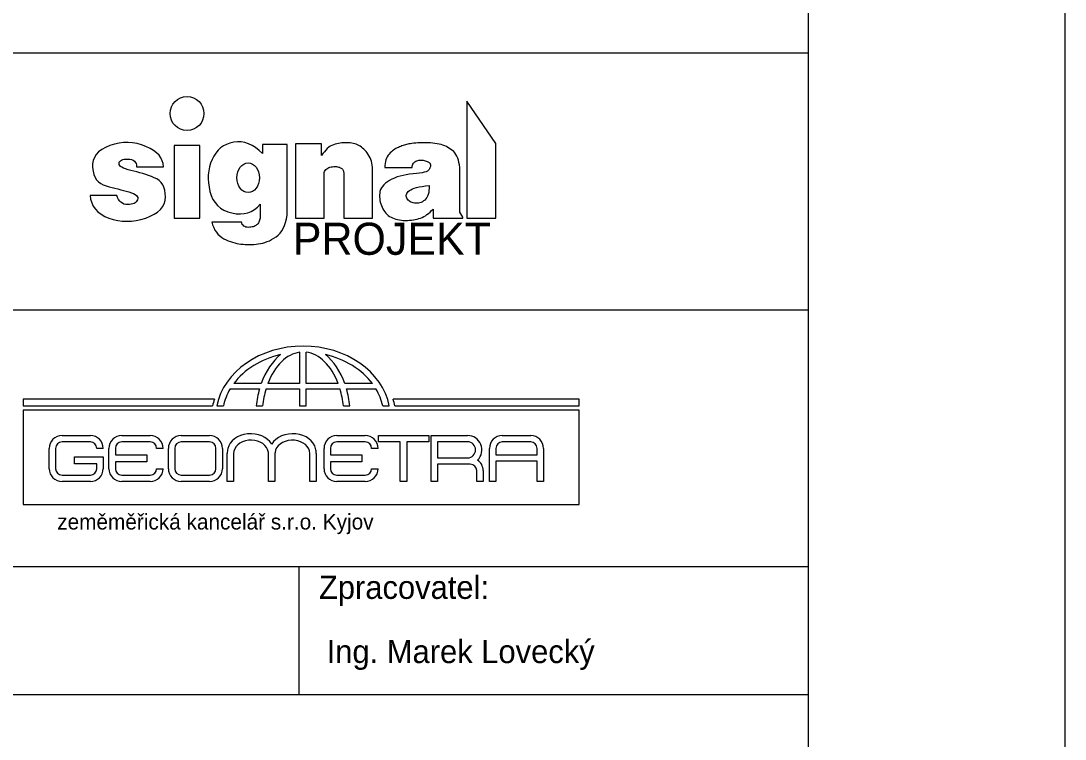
# Model space of a CAD drawing. Extents: x 3181 to 4881, y -3400 to -2956.
# Drawn here: x 4054.2 to 4135.6, y -3301.1 to -3245.1 of the extents above; entities that cross this region are included whole.
import ezdxf

# ---------------------------------------------------------------- set-up
doc = ezdxf.new("R2010")
doc.units = 0
for name, color, linetype in [('Default', 7, 'Continuous'), ('Vrstva 1', 7, 'Continuous'), ('Vrstva 11', 7, 'Continuous'), ('Vrstva 17', 7, 'Continuous'), ('Vrstva 6', 7, 'Continuous')]:
    doc.layers.add(name, color=color, linetype=linetype)

msp = doc.modelspace()

# ---------------------------------------------------------------- linework, layer by layer
at = {"layer": 'Default'}
msp.add_lwpolyline([(3925.563, -3399.617), (4135.563, -3399.617), (4135.563, -3102.617), (3925.563, -3102.617)], close=True, dxfattribs=at)
at = {"layer": 'Vrstva 1'}
msp.add_lwpolyline([(3945.563, -3122.617), (4115.563, -3122.617), (4115.563, -3382.617), (3945.563, -3382.617)], close=True, dxfattribs=at)
at = {"layer": 'Vrstva 11'}
for points in [[(4091.228, -3260.496), (4091.228, -3254.656), (4088.988, -3251.376), (4088.988, -3260.496), (4091.228, -3260.496)], [(4062.499, -3260.731), (4062.861, -3260.714), (4063.228, -3260.666), (4063.599, -3260.587), (4063.975, -3260.477), (4064.329, -3260.341), (4064.637, -3260.185), (4064.898, -3260.009), (4065.112, -3259.813), (4065.28, -3259.597), (4065.4, -3259.361), (4065.474, -3259.105), (4065.5, -3258.829), (4065.49, -3258.556), (4065.451, -3258.307), (4065.385, -3258.083), (4065.291, -3257.883), (4065.17, -3257.708), (4065.021, -3257.558), (4064.844, -3257.433), (4064.639, -3257.332), (4064.42, -3257.246), (4064.198, -3257.164), (4063.973, -3257.087), (4063.747, -3257.014), (4063.518, -3256.946), (4063.287, -3256.881), (4063.054, -3256.822), (4062.818, -3256.766), (4062.596, -3256.711), (4062.405, -3256.652), (4062.244, -3256.589), (4062.114, -3256.522), (4062.014, -3256.451), (4061.945, -3256.376), (4061.906, -3256.297), (4061.897, -3256.214), (4061.914, -3256.134), (4061.95, -3256.065), (4062.006, -3256.007), (4062.082, -3255.96), (4062.178, -3255.924), (4062.294, -3255.898), (4062.429, -3255.884), (4062.585, -3255.88), (4062.74, -3255.891), (4062.875, -3255.92), (4062.99, -3255.967), (4063.085, -3256.033), (4063.16, -3256.117), (4063.214, -3256.219), (4063.249, -3256.339), (4063.263, -3256.478), (4065.342, -3256.478), (4065.323, -3256.236), (4065.261, -3256.007), (4065.156, -3255.789), (4065.008, -3255.585), (4064.817, -3255.394), (4064.583, -3255.215), (4064.307, -3255.049), (4063.987, -3254.895), (4063.645, -3254.766), (4063.3, -3254.671), (4062.952, -3254.612), (4062.602, -3254.587), (4062.249, -3254.597), (4061.894, -3254.642), (4061.535, -3254.721), (4061.174, -3254.836), (4060.836, -3254.978), (4060.547, -3255.141), (4060.306, -3255.324), (4060.114, -3255.528), (4059.971, -3255.753), (4059.876, -3255.997), (4059.83, -3256.263), (4059.832, -3256.549), (4059.872, -3256.83), (4059.938, -3257.082), (4060.03, -3257.305), (4060.148, -3257.497), (4060.293, -3257.661), (4060.464, -3257.795), (4060.661, -3257.899), (4060.885, -3257.974), (4061.12, -3258.034), (4061.351, -3258.093), (4061.578, -3258.152), (4061.802, -3258.211), (4062.023, -3258.27), (4062.239, -3258.328), (4062.452, -3258.386), (4062.662, -3258.444), (4062.854, -3258.504), (4063.016, -3258.568), (4063.146, -3258.637), (4063.246, -3258.711), (4063.314, -3258.789), (4063.352, -3258.871), (4063.359, -3258.958), (4063.335, -3259.049), (4063.289, -3259.137), (4063.228, -3259.214), (4063.152, -3259.278), (4063.062, -3259.331), (4062.958, -3259.373), (4062.84, -3259.403), (4062.707, -3259.421), (4062.559, -3259.428), (4062.411, -3259.418), (4062.275, -3259.384), (4062.152, -3259.329), (4062.04, -3259.25), (4061.942, -3259.149), (4061.855, -3259.025), (4061.781, -3258.879), (4061.72, -3258.71), (4059.639, -3258.71), (4059.683, -3259.017), (4059.767, -3259.299), (4059.89, -3259.557), (4060.052, -3259.791), (4060.254, -3260), (4060.496, -3260.185), (4060.778, -3260.346), (4061.099, -3260.483), (4061.442, -3260.592), (4061.79, -3260.669), (4062.142, -3260.716), (4062.499, -3260.731)], [(4068.188, -3260.496), (4068.188, -3254.816), (4066.188, -3254.816), (4066.188, -3260.496), (4068.188, -3260.496)], [(4072.047, -3262.538), (4072.216, -3262.534), (4072.386, -3262.526), (4072.558, -3262.512), (4072.731, -3262.494), (4072.905, -3262.467), (4073.079, -3262.428), (4073.253, -3262.377), (4073.426, -3262.314), (4073.6, -3262.238), (4073.772, -3262.15), (4073.945, -3262.051), (4074.117, -3261.939), (4074.282, -3261.809), (4074.43, -3261.656), (4074.563, -3261.481), (4074.679, -3261.282), (4074.78, -3261.06), (4074.865, -3260.815), (4074.934, -3260.547), (4074.988, -3260.256), (4074.988, -3254.736), (4073.068, -3254.736), (4073.068, -3255.456), (4072.802, -3255.201), (4072.531, -3254.988), (4072.257, -3254.816), (4071.978, -3254.685), (4071.695, -3254.595), (4071.407, -3254.546), (4071.116, -3254.539), (4070.82, -3254.572), (4070.533, -3254.64), (4070.267, -3254.737), (4070.024, -3254.863), (4069.802, -3255.016), (4069.602, -3255.199), (4069.423, -3255.41), (4069.267, -3255.649), (4069.132, -3255.917), (4069.022, -3256.203), (4068.937, -3256.496), (4068.878, -3256.796), (4068.845, -3257.103), (4068.838, -3257.418), (4068.857, -3257.74), (4068.901, -3258.068), (4068.972, -3258.405), (4069.072, -3258.728), (4069.205, -3259.019), (4069.37, -3259.277), (4069.568, -3259.502), (4069.799, -3259.695), (4070.062, -3259.855), (4070.358, -3259.982), (4070.687, -3260.077), (4071.023, -3260.135), (4071.342, -3260.152), (4071.643, -3260.129), (4071.926, -3260.065), (4072.191, -3259.96), (4072.438, -3259.815), (4072.668, -3259.628), (4072.88, -3259.402), (4072.88, -3260.478), (4072.861, -3260.566), (4072.838, -3260.648), (4072.81, -3260.723), (4072.778, -3260.794), (4072.742, -3260.858), (4072.701, -3260.917), (4072.655, -3260.97), (4072.605, -3261.017), (4072.55, -3261.059), (4072.487, -3261.095), (4072.417, -3261.126), (4072.34, -3261.152), (4072.256, -3261.172), (4072.165, -3261.187), (4072.067, -3261.196), (4071.962, -3261.2), (4071.858, -3261.195), (4071.765, -3261.176), (4071.682, -3261.144), (4071.609, -3261.099), (4071.546, -3261.041), (4071.493, -3260.969), (4071.451, -3260.884), (4071.418, -3260.786), (4069.111, -3260.786), (4069.18, -3261.014), (4069.264, -3261.223), (4069.361, -3261.413), (4069.472, -3261.584), (4069.596, -3261.737), (4069.735, -3261.871), (4069.887, -3261.986), (4070.053, -3262.082), (4070.225, -3262.165), (4070.396, -3262.239), (4070.565, -3262.305), (4070.733, -3262.362), (4070.899, -3262.41), (4071.064, -3262.45), (4071.227, -3262.481), (4071.389, -3262.504), (4071.551, -3262.52), (4071.715, -3262.531), (4071.88, -3262.537), (4072.047, -3262.538)], [(4081.628, -3260.496), (4081.628, -3256.696), (4081.624, -3256.526), (4081.61, -3256.363), (4081.586, -3256.206), (4081.55, -3256.056), (4081.504, -3255.912), (4081.447, -3255.776), (4081.379, -3255.645), (4081.301, -3255.522), (4081.216, -3255.405), (4081.129, -3255.297), (4081.04, -3255.197), (4080.949, -3255.106), (4080.856, -3255.022), (4080.761, -3254.947), (4080.664, -3254.88), (4080.565, -3254.821), (4080.462, -3254.77), (4080.356, -3254.725), (4080.245, -3254.688), (4080.13, -3254.658), (4080.011, -3254.634), (4079.887, -3254.617), (4079.759, -3254.608), (4079.627, -3254.605), (4079.493, -3254.608), (4079.361, -3254.616), (4079.229, -3254.629), (4079.099, -3254.647), (4078.97, -3254.67), (4078.842, -3254.698), (4078.716, -3254.731), (4078.59, -3254.769), (4078.467, -3254.817), (4078.345, -3254.882), (4078.226, -3254.963), (4078.11, -3255.061), (4077.996, -3255.175), (4077.884, -3255.305), (4077.775, -3255.452), (4077.668, -3255.616), (4077.668, -3254.696), (4075.628, -3254.696), (4075.628, -3260.496), (4077.868, -3260.496), (4077.868, -3256.936), (4077.902, -3256.845), (4077.946, -3256.764), (4078.001, -3256.693), (4078.065, -3256.632), (4078.139, -3256.581), (4078.223, -3256.54), (4078.317, -3256.509), (4078.421, -3256.488), (4078.527, -3256.475), (4078.628, -3256.468), (4078.723, -3256.467), (4078.814, -3256.472), (4078.899, -3256.484), (4078.978, -3256.501), (4079.053, -3256.525), (4079.122, -3256.555), (4079.184, -3256.589), (4079.238, -3256.628), (4079.284, -3256.67), (4079.321, -3256.716), (4079.35, -3256.765), (4079.371, -3256.818), (4079.383, -3256.875), (4079.388, -3256.936), (4079.388, -3260.496), (4081.628, -3260.496)], [(4084.19, -3260.66), (4084.352, -3260.657), (4084.51, -3260.648), (4084.663, -3260.634), (4084.812, -3260.614), (4084.956, -3260.588), (4085.097, -3260.556), (4085.233, -3260.519), (4085.364, -3260.476), (4085.493, -3260.425), (4085.62, -3260.363), (4085.746, -3260.292), (4085.869, -3260.209), (4085.991, -3260.116), (4086.112, -3260.013), (4086.23, -3259.9), (4086.348, -3259.776), (4086.348, -3260.496), (4088.668, -3260.496), (4088.668, -3260.416), (4088.428, -3260.016), (4088.428, -3256.536), (4088.401, -3256.331), (4088.365, -3256.141), (4088.32, -3255.965), (4088.265, -3255.804), (4088.201, -3255.657), (4088.127, -3255.525), (4088.043, -3255.407), (4087.95, -3255.304), (4087.849, -3255.211), (4087.742, -3255.125), (4087.628, -3255.047), (4087.508, -3254.975), (4087.382, -3254.91), (4087.25, -3254.852), (4087.111, -3254.8), (4086.966, -3254.756), (4086.814, -3254.718), (4086.655, -3254.686), (4086.489, -3254.66), (4086.315, -3254.639), (4086.135, -3254.624), (4085.947, -3254.615), (4085.751, -3254.611), (4085.549, -3254.613), (4085.35, -3254.619), (4085.166, -3254.627), (4084.997, -3254.638), (4084.843, -3254.651), (4084.703, -3254.666), (4084.578, -3254.683), (4084.467, -3254.702), (4084.372, -3254.724), (4084.283, -3254.748), (4084.194, -3254.773), (4084.104, -3254.801), (4084.013, -3254.83), (4083.921, -3254.862), (4083.829, -3254.895), (4083.737, -3254.931), (4083.643, -3254.968), (4083.55, -3255.01), (4083.458, -3255.058), (4083.366, -3255.114), (4083.276, -3255.176), (4083.187, -3255.245), (4083.099, -3255.321), (4083.012, -3255.403), (4082.926, -3255.493), (4082.845, -3255.59), (4082.776, -3255.697), (4082.718, -3255.814), (4082.67, -3255.939), (4082.633, -3256.074), (4082.607, -3256.219), (4082.592, -3256.373), (4082.588, -3256.536), (4084.708, -3256.536), (4084.723, -3256.439), (4084.747, -3256.352), (4084.78, -3256.274), (4084.821, -3256.205), (4084.872, -3256.146), (4084.93, -3256.095), (4084.998, -3256.054), (4085.073, -3256.021), (4085.154, -3255.997), (4085.235, -3255.979), (4085.317, -3255.968), (4085.399, -3255.963), (4085.481, -3255.965), (4085.565, -3255.973), (4085.648, -3255.988), (4085.732, -3256.009), (4085.813, -3256.035), (4085.884, -3256.063), (4085.947, -3256.092), (4086, -3256.124), (4086.045, -3256.159), (4086.082, -3256.195), (4086.109, -3256.233), (4086.128, -3256.274), (4086.14, -3256.317), (4086.145, -3256.363), (4086.144, -3256.411), (4086.136, -3256.463), (4086.122, -3256.517), (4086.103, -3256.574), (4086.076, -3256.634), (4086.044, -3256.696), (4085.993, -3256.757), (4085.912, -3256.813), (4085.801, -3256.864), (4085.659, -3256.909), (4085.487, -3256.949), (4085.285, -3256.984), (4085.052, -3257.014), (4084.789, -3257.038), (4084.517, -3257.064), (4084.258, -3257.102), (4084.01, -3257.15), (4083.775, -3257.208), (4083.553, -3257.277), (4083.342, -3257.357), (4083.144, -3257.447), (4082.958, -3257.547), (4082.789, -3257.656), (4082.641, -3257.768), (4082.513, -3257.885), (4082.407, -3258.007), (4082.321, -3258.133), (4082.256, -3258.264), (4082.212, -3258.399), (4082.189, -3258.539), (4082.181, -3258.68), (4082.182, -3258.82), (4082.192, -3258.959), (4082.211, -3259.097), (4082.239, -3259.234), (4082.276, -3259.369), (4082.322, -3259.504), (4082.377, -3259.637), (4082.44, -3259.765), (4082.51, -3259.884), (4082.587, -3259.995), (4082.671, -3260.096), (4082.761, -3260.189), (4082.859, -3260.273), (4082.964, -3260.347), (4083.075, -3260.413), (4083.193, -3260.471), (4083.317, -3260.521), (4083.447, -3260.564), (4083.584, -3260.598), (4083.726, -3260.625), (4083.875, -3260.644), (4084.03, -3260.656), (4084.19, -3260.66)], [(4084.906, -3259.315), (4084.803, -3259.295), (4084.708, -3259.267), (4084.622, -3259.231), (4084.543, -3259.187), (4084.472, -3259.136), (4084.409, -3259.077), (4084.354, -3259.01), (4084.307, -3258.935), (4084.273, -3258.858), (4084.255, -3258.781), (4084.254, -3258.705), (4084.27, -3258.63), (4084.302, -3258.555), (4084.351, -3258.482), (4084.417, -3258.41), (4084.5, -3258.338), (4084.603, -3258.27), (4084.732, -3258.207), (4084.886, -3258.149), (4085.065, -3258.097), (4085.269, -3258.05), (4085.498, -3258.008), (4085.753, -3257.971), (4086.032, -3257.94), (4086.037, -3258.139), (4086.028, -3258.321), (4086.006, -3258.487), (4085.972, -3258.636), (4085.924, -3258.77), (4085.864, -3258.887), (4085.79, -3258.989), (4085.704, -3259.074), (4085.611, -3259.145), (4085.515, -3259.205), (4085.418, -3259.252), (4085.319, -3259.288), (4085.219, -3259.313), (4085.116, -3259.325), (4085.012, -3259.326), (4084.906, -3259.315)]]:
    msp.add_lwpolyline(points, dxfattribs=at)
msp.add_circle((4067.188, -3252.336), 1.32, dxfattribs=at)
msp.add_ellipse((4071.948, -3257.336), major_axis=(0, 1.16), ratio=0.758621, dxfattribs=at)
at = {"layer": 'Vrstva 17'}
for p, q in [((4075.958, -3270.929), (4075.958, -3273.375)), ((4076.465, -3273.375), (4076.465, -3270.927)), ((4072.965, -3273.375), (4070.82, -3273.375)), ((4075.958, -3273.375), (4073.482, -3273.375)), ((4078.96, -3273.375), (4076.465, -3273.375)), ((4081.622, -3273.375), (4079.477, -3273.375)), ((4070.545, -3273.787), (4072.832, -3273.787)), ((4073.342, -3273.787), (4075.958, -3273.787)), ((4075.958, -3273.787), (4075.958, -3275.107)), ((4076.465, -3275.107), (4076.465, -3273.787)), ((4076.465, -3273.787), (4079.099, -3273.787)), ((4079.609, -3273.787), (4081.897, -3273.787)), ((4069.314, -3274.576), (4054.433, -3274.576)), ((4054.433, -3274.576), (4054.433, -3275.107)), ((4054.433, -3275.107), (4069.176, -3275.107)), ((4069.502, -3275.107), (4070.019, -3275.107)), ((4072.575, -3275.107), (4073.075, -3275.107)), ((4075.958, -3275.107), (4076.465, -3275.107)), ((4079.366, -3275.107), (4079.866, -3275.107)), ((4082.423, -3275.107), (4082.94, -3275.107)), ((4097.712, -3274.576), (4083.233, -3274.576)), ((4083.371, -3275.107), (4097.712, -3275.107)), ((4097.712, -3275.107), (4097.712, -3274.576)), ((4097.71, -3275.451), (4054.427, -3275.451)), ((4054.427, -3275.451), (4054.427, -3282.789)), ((4097.71, -3282.789), (4097.71, -3275.451)), ((4057.452, -3277.417), (4059.663, -3277.417)), ((4062.108, -3277.417), (4064.319, -3277.417)), ((4066.732, -3277.417), (4068.943, -3277.417)), ((4078.851, -3277.417), (4081.061, -3277.417)), ((4086.188, -3277.417), (4089.032, -3277.417)), ((4091.736, -3277.417), (4093.947, -3277.417)), ((4056.454, -3280.001), (4056.454, -3278.415)), ((4056.953, -3278.415), (4056.953, -3280.001)), ((4059.663, -3277.916), (4057.452, -3277.916)), ((4060.66, -3278.415), (4060.162, -3278.415)), ((4061.11, -3280.001), (4061.11, -3278.415)), ((4061.609, -3278.415), (4061.609, -3278.926)), ((4064.319, -3277.916), (4062.108, -3277.916)), ((4065.317, -3278.415), (4064.818, -3278.415)), ((4065.734, -3280.001), (4065.734, -3278.415)), ((4066.233, -3278.415), (4066.233, -3280.001)), ((4068.943, -3277.916), (4066.732, -3277.916)), ((4069.442, -3280.001), (4069.442, -3278.415)), ((4069.941, -3278.415), (4069.941, -3280.001)), ((4077.853, -3280.001), (4077.853, -3278.415)), ((4078.352, -3278.415), (4078.352, -3278.926)), ((4081.061, -3277.916), (4078.851, -3277.916)), ((4082.059, -3278.415), (4081.56, -3278.415)), ((4083.794, -3280.999), (4083.794, -3277.904)), ((4084.297, -3277.904), (4084.297, -3280.999)), ((4089.032, -3277.906), (4086.692, -3277.906)), ((4086.692, -3277.906), (4086.692, -3279.156)), ((4090.738, -3280.999), (4090.738, -3278.415)), ((4091.237, -3278.415), (4091.237, -3278.924)), ((4093.947, -3277.916), (4091.736, -3277.916)), ((4094.446, -3278.924), (4094.446, -3278.415)), ((4094.945, -3278.415), (4094.945, -3280.999)), ((4058.427, -3279.623), (4058.427, -3279.079)), ((4058.427, -3279.079), (4060.66, -3279.079)), ((4060.66, -3279.079), (4060.66, -3280.001)), ((4061.609, -3278.926), (4064.052, -3278.926)), ((4064.052, -3278.926), (4064.052, -3279.47)), ((4070.313, -3280.999), (4070.313, -3278.814)), ((4070.814, -3278.814), (4070.814, -3280.999)), ((4073.533, -3280.999), (4073.533, -3278.814)), ((4074.033, -3278.814), (4074.033, -3280.999)), ((4076.752, -3280.999), (4076.752, -3278.814)), ((4077.253, -3278.814), (4077.253, -3280.999)), ((4078.352, -3278.926), (4080.795, -3278.926)), ((4080.795, -3278.926), (4080.795, -3279.47)), ((4086.692, -3279.156), (4089.032, -3279.156)), ((4091.237, -3278.924), (4094.446, -3278.924)), ((4060.162, -3279.623), (4058.427, -3279.623)), ((4060.162, -3280.001), (4060.162, -3279.623)), ((4064.052, -3279.47), (4061.609, -3279.47)), ((4061.609, -3279.47), (4061.609, -3280.001)), ((4064.818, -3280.001), (4065.317, -3280.001)), ((4080.795, -3279.47), (4078.352, -3279.47)), ((4078.352, -3279.47), (4078.352, -3280.001)), ((4081.56, -3280.001), (4082.059, -3280.001)), ((4089.032, -3279.645), (4086.692, -3279.645)), ((4089.247, -3279.649), (4089.032, -3279.645)), ((4089.746, -3280.999), (4089.746, -3280.148)), ((4090.244, -3280.148), (4090.244, -3280.999)), ((4094.446, -3279.427), (4091.237, -3279.427)), ((4091.237, -3279.427), (4091.237, -3280.999)), ((4094.446, -3280.999), (4094.446, -3279.427)), ((4057.452, -3280.5), (4059.663, -3280.5)), ((4062.108, -3280.5), (4064.319, -3280.5)), ((4066.732, -3280.5), (4068.943, -3280.5)), ((4078.851, -3280.5), (4081.061, -3280.5)), ((4059.663, -3280.999), (4057.452, -3280.999)), ((4064.319, -3280.999), (4062.108, -3280.999)), ((4068.943, -3280.999), (4066.732, -3280.999)), ((4070.814, -3280.999), (4070.313, -3280.999)), ((4074.033, -3280.999), (4073.533, -3280.999)), ((4077.253, -3280.999), (4076.752, -3280.999)), ((4081.061, -3280.999), (4078.851, -3280.999)), ((4084.297, -3280.999), (4083.794, -3280.999)), ((4090.244, -3280.999), (4089.746, -3280.999)), ((4091.237, -3280.999), (4090.738, -3280.999)), ((4094.945, -3280.999), (4094.446, -3280.999)), ((4054.427, -3282.789), (4097.71, -3282.789))]:
    msp.add_line(p, q, dxfattribs=at)
for points in [[(4083.794, -3277.904), (4082.096, -3277.904), (4082.096, -3277.417), (4086.009, -3277.417)], [(4086.009, -3277.417), (4086.009, -3277.904), (4084.297, -3277.904)], [(4086.692, -3279.645), (4086.692, -3280.999), (4086.188, -3280.999), (4086.188, -3277.417)]]:
    msp.add_lwpolyline(points, dxfattribs=at)
for centre, radius, start, end in [((4057.452, -3278.415), 0.998, 90, 180), ((4059.663, -3278.415), 0.998, 360, 90), ((4062.108, -3278.415), 0.998, 90, 180), ((4064.319, -3278.415), 0.998, 360, 90), ((4066.732, -3278.415), 0.998, 90, 180), ((4068.943, -3278.415), 0.998, 360, 90), ((4078.851, -3278.415), 0.998, 90, 180), ((4081.061, -3278.415), 0.998, 360, 90), ((4089.032, -3278.531), 1.114, 314.45734, 90), ((4091.736, -3278.415), 0.998, 90, 180), ((4093.947, -3278.415), 0.998, 360, 90), ((4057.452, -3278.415), 0.499, 90, 180), ((4059.663, -3278.415), 0.499, 0, 90), ((4062.108, -3278.415), 0.499, 90, 180), ((4064.319, -3278.415), 0.499, 0, 90), ((4066.732, -3278.415), 0.499, 90, 180), ((4068.943, -3278.415), 0.499, 0, 90), ((4072.25, -3278.864), 1.938, 166.96576, 178.52091), ((4072.579, -3278.879), 0.957, 3.86486, 22.41569), ((4075.315, -3278.864), 1.938, 1.47909, 13.03424), ((4078.851, -3278.415), 0.499, 90, 180), ((4081.061, -3278.415), 0.499, 0, 90), ((4089.032, -3278.531), 0.625, 270, 90), ((4091.736, -3278.415), 0.499, 90, 180), ((4093.947, -3278.415), 0.499, 0, 90), ((4075.266, -3278.936), 1.238, 162.61388, 174.3506), ((4089.247, -3280.148), 0.998, 360, 55.44734), ((4057.452, -3280.001), 0.998, 180, 270), ((4057.452, -3280.001), 0.499, 180, 270), ((4059.663, -3280.001), 0.998, 270, 0), ((4059.663, -3280.001), 0.499, 270, 0), ((4062.108, -3280.001), 0.998, 180, 270), ((4062.108, -3280.001), 0.499, 180, 270), ((4064.319, -3280.001), 0.998, 270, 0), ((4064.319, -3280.001), 0.499, 270, 0), ((4066.732, -3280.001), 0.998, 180, 270), ((4066.732, -3280.001), 0.499, 180, 270), ((4068.943, -3280.001), 0.998, 270, 0), ((4068.943, -3280.001), 0.499, 270, 0), ((4078.851, -3280.001), 0.998, 180, 270), ((4078.851, -3280.001), 0.499, 180, 270), ((4081.061, -3280.001), 0.998, 270, 0), ((4081.061, -3280.001), 0.499, 270, 0), ((4089.247, -3280.148), 0.499, 0, 90)]:
    msp.add_arc(centre, radius, start, end, dxfattribs=at)
for centre, major_axis, ratio, start_param, end_param in [((4076.221, -3275.979), (-6.804, 0), 0.811768, 3.300239, 6.124539), ((4076.221, -3275.979), (-6.296, 0), 0.804826, 4.992897, 5.743383), ((4076.221, -3275.979), (0, 5.524), 0.668443, 0.491666, 1.079789), ((4076.221, -3275.979), (0, 5.067), 0.630136, 0.08224, 1.030995), ((4076.221, -3275.979), (0, 5.067), 0.630136, 5.252191, 6.206521), ((4076.221, -3275.979), (0, 5.524), 0.668443, 5.203397, 5.79152), ((4076.221, -3275.979), (-6.296, 0), 0.804826, 3.681394, 4.431881), ((4076.221, -3275.979), (-6.296, 0), 0.804826, 5.835664, 6.110118), ((4076.221, -3275.979), (0, 5.524), 0.668443, 1.16256, 1.41215), ((4076.221, -3275.979), (0, 5.067), 0.630136, 1.123275, 1.397729), ((4076.221, -3275.979), (0, 5.067), 0.630136, 4.885456, 5.159911), ((4076.221, -3275.979), (0, 5.524), 0.668443, 4.871035, 5.120625), ((4076.221, -3275.979), (-6.296, 0), 0.804826, 3.31466, 3.589114), ((4075.895, -3275.979), (-6.804, 0), 0.811768, 6.026233, 6.124539), ((4076.653, -3275.979), (-6.804, 0), 0.811768, 3.300239, 3.398545), ((4072.142, -3278.659), (1.805, 0), 0.766187, 0.429647, 2.97338), ((4072.167, -3278.814), (1.354, 0), 0.766187, 0.29376, 3.141593), ((4075.424, -3278.659), (-1.805, 0), 0.766187, 3.309805, 5.853538), ((4075.398, -3278.814), (-1.354, 0), 0.766187, 3.141593, 6.041607)]:
    msp.add_ellipse(centre, major_axis=major_axis, ratio=ratio, start_param=start_param, end_param=end_param, dxfattribs=at)
at = {"layer": 'Vrstva 6'}
for p, q in [((3945.563, -3267.617), (4115.563, -3267.617)), ((3945.563, -3287.617), (4115.563, -3287.617)), ((4075.913, -3297.617), (4075.913, -3287.617))]:
    msp.add_line(p, q, dxfattribs=at)
msp.add_lwpolyline([(3945.563, -3247.617), (4115.563, -3247.617), (4115.563, -3297.617), (3945.563, -3297.617)], close=True, dxfattribs=at)

# ---------------------------------------------------------------- texts
at = {"layer": 'Vrstva 11'}
msp.add_text('PROJEKT', height=2.5, dxfattribs=at).set_placement((4075.428, -3263.339))
at = {"layer": 'Vrstva 17'}
msp.add_text('zeměměřická kancelář s.r.o. Kyjov', height=1.20984, dxfattribs=at).set_placement((4057.079, -3284.738))
at = {"layer": 'Vrstva 6'}
for s, p in [('Zpracovatel:', (4077.459, -3290.143)), ('Ing. Marek Lovecký', (4078.06, -3295.143))]:
    msp.add_text(s, height=1.8, dxfattribs=at).set_placement(p)

doc.saveas('drawing.dxf')
